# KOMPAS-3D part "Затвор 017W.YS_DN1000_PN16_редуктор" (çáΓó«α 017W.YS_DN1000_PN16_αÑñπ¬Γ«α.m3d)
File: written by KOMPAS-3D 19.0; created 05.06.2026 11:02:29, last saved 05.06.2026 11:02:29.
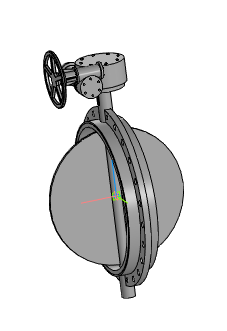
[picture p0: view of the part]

Document properties: Автор: Энергия; Полное имя файла: ..\..\..\3d для проектировщиков\x.x Тип 017W.Y(S) Затвор дисковый поворотный межфланцевый\Затвор 017W.Y(S)_DN50-DN1200_редуктор\Затвор 017W.YS_DN1000_PN16_редуктор.a3d

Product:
- Part/product: Затвор 017W.YS_DN1000_PN16_редуктор
    Масса: 680.666

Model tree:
1. Операция без истории:1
